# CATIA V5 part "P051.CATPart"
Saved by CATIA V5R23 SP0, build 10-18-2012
Part number: P051
Definition: Tas
Bounding box of the stored display mesh (mm): x -28 to 28, y -20 to 20, z 0 to 35
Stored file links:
  C:\wamp\www\COURS\CONCEPTION GMP1\TITRE 02-SEMESTRE 2\03-TP7-PRESSE MECANIQUE\eleve\P051.CATPart
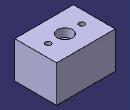
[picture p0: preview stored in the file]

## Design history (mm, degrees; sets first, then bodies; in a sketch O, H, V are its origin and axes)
Set1
  Line1 "Axe X": stored without definition
Body1 (main body)
  Sketch1 on xy-plane, origin (0, 0, 0), H (1, 0, 0), V (0, 1, 0)
    line L1 (-28, 20) -> (28, 20)
    line L2 (28, 20) -> (28, -20)
    line L3 (28, -20) -> (-28, -20)
    line L4 (-28, -20) -> (-28, 20)
    length L1 = 56
    length L2 = 40
    horizontal: L1 H, L3 H
    vertical: L2 V, L4 V
    symmetry: L2 L4 V, L1 L3 H
  Pad1: profile Sketch1, direction (0, 0, 1), length 35
  Sketch2 on face of Pad1, origin (-0.5971, 7.1965, 35), H (1, 0, 0), V (0, 1, 0)
    point P1 (0.5971, -7.1965)
    reference intersected line E1 through (0, -7.1965) direction (-1, 0) from zx-plane
    reference intersected line E2 through (0.5971, 0) direction (0, 1) from yz-plane
    coincidence: P1 E1, P1 E2
  Hole1: placed by Sketch2, at (0, 0, 35) direction (0, 0, -1), diameter 6.647, through (limit type 3), counterbore diameter 14, counterbore depth 8, threaded "M8", thread diameter 8, thread depth 10, pitch 1.25
  Sketch3 on face of Pad1, origin (-15.9576, 4.3327, 35), H (1, 0, 0), V (0, 1, 0)
    point P1 (-0.0424, -4.3327)
    reference intersected line E1 through (0, -4.3327) direction (-1, 0) from zx-plane
    reference intersected line E2 through (15.9576, 0) direction (0, 1) from yz-plane
    distance P1 E2 = 16
    coincidence: P1 E1
  Hole2: placed by Sketch3, at (-16, 0, 35) direction (0, 0, -1), diameter 5, through (limit type 3)
  RectPattern1: of Hole2, direction 1 instances 2, spacing 32, along Line1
